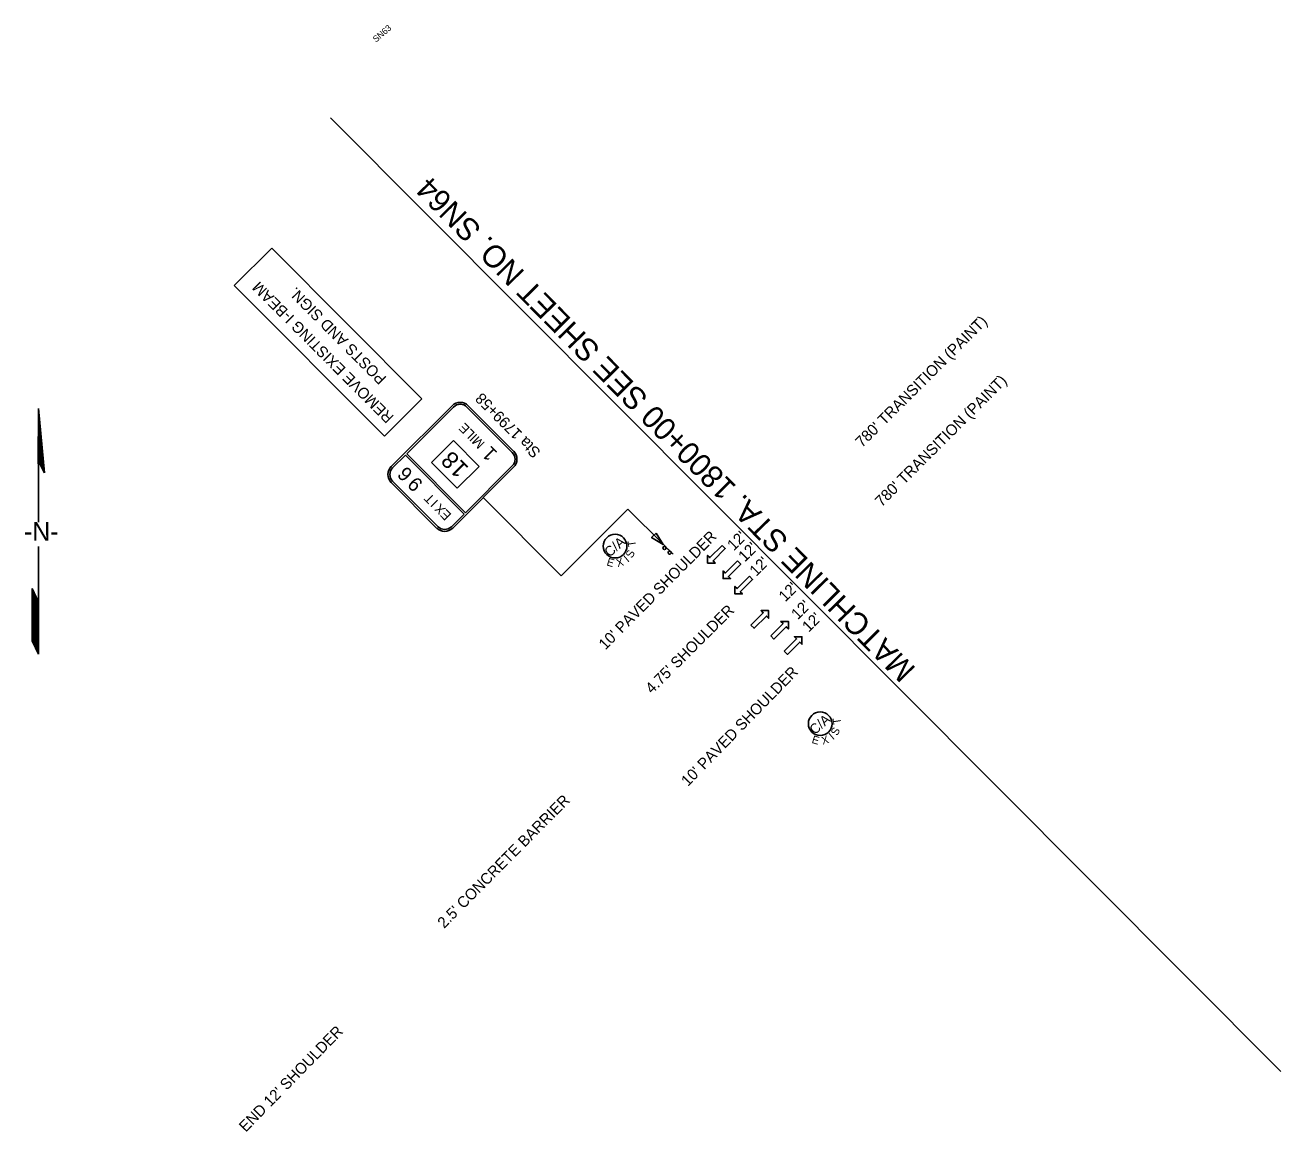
# Model space of a CAD drawing. Extents: x 1824788 to 1826426, y 1192883 to 1194457.
# Drawn here: x 1825629 to 1826426, y 1193755 to 1194457 of the extents above; entities that cross this region are included whole.
import ezdxf

# ---------------------------------------------------------------- set-up
doc = ezdxf.new("R2010")
doc.units = 0
for name, color, linetype in [('RD_HC_TX_Sta50', 7, 'Continuous'), ('RD_PD_Final_LnLine', 7, 'Continuous'), ('RD_PD_Final_TX', 7, 'Continuous'), ('RD_SHT_MatchLine', 7, 'Continuous'), ('RD_SHT_TX', 7, 'Continuous'), ('RD_Sketch1', 7, 'Continuous'), ('RD_Sketch8', 7, 'Continuous'), ('SN_P_Signs', 7, 'Continuous')]:
    doc.layers.add(name, color=color, linetype=linetype)

# ---------------------------------------------------------------- blocks, each defined once
blk = doc.blocks.new('SARRW2')
at = {"layer": 'RD_PD_Final_LnLine'}
blk.add_lwpolyline([(-12, 1.2), (-12, -1.2), (-2.83, -1.2), (-2.83, -2.83), (0, 0), (-2.83, 2.83), (-2.83, 1.2)], close=True, dxfattribs=at)

msp = doc.modelspace()

# ---------------------------------------------------------------- linework, layer by layer
at = {"layer": 'RD_SHT_MatchLine'}
msp.add_line((1825823.21, 1194398.41), (1826426.49, 1193793.21), dxfattribs=at)
at = {"layer": 'RD_Sketch1'}
for p, q in [((1825637.73, 1194213.93), (1825637.53, 1194178.77)), ((1825641.46, 1194173.23), (1825637.73, 1194213.93)), ((1825638.04, 1194180.17), (1825641.46, 1194173.23)), ((1825637.73, 1194179.06), (1825637.73, 1194157.24)), ((1825637.73, 1194157.24), (1825637.73, 1194141.77)), ((1825637.73, 1194126.32), (1825637.73, 1194100.55)), ((1825637.73, 1194100.55), (1825637.73, 1194058.03)), ((1825633.74, 1194085.49), (1825633.74, 1194099.66)), ((1825633.74, 1194099.66), (1825637.73, 1194091.1)), ((1825633.74, 1194066.59), (1825633.74, 1194085.49)), ((1825637.73, 1194058.03), (1825633.74, 1194066.59))]:
    msp.add_line(p, q, dxfattribs=at)
for points in [[(1825637.75, 1194179.37), (1825637.75, 1194213.81)], [(1825637.84, 1194179.63), (1825637.84, 1194212.78)], [(1825637.93, 1194179.89), (1825637.94, 1194211.75)], [(1825638.03, 1194180.15), (1825638.03, 1194210.71)], [(1825638.12, 1194180), (1825638.12, 1194209.68)], [(1825638.22, 1194179.81), (1825638.22, 1194208.65)], [(1825638.31, 1194179.61), (1825638.31, 1194207.62)], [(1825638.41, 1194179.42), (1825638.41, 1194206.58)], [(1825638.5, 1194179.23), (1825638.5, 1194205.55)], [(1825638.6, 1194179.04), (1825638.6, 1194204.52)], [(1825637.65, 1194179.11), (1825637.65, 1194199.89)], [(1825638.69, 1194178.85), (1825638.69, 1194203.49)], [(1825638.79, 1194178.66), (1825638.79, 1194202.45)], [(1825638.88, 1194178.46), (1825638.88, 1194201.42)], [(1825638.97, 1194178.27), (1825638.97, 1194200.39)], [(1825639.07, 1194178.08), (1825639.07, 1194199.36)], [(1825639.16, 1194177.89), (1825639.16, 1194198.32)], [(1825639.26, 1194177.7), (1825639.26, 1194197.29)], [(1825639.35, 1194177.51), (1825639.35, 1194196.26)], [(1825639.45, 1194177.31), (1825639.45, 1194195.23)], [(1825639.54, 1194177.12), (1825639.54, 1194194.19)], [(1825639.64, 1194176.93), (1825639.64, 1194193.16)], [(1825639.73, 1194176.74), (1825639.73, 1194192.13)], [(1825639.82, 1194176.55), (1825639.82, 1194191.1)], [(1825639.92, 1194176.35), (1825639.92, 1194190.06)], [(1825640.01, 1194176.16), (1825640.01, 1194189.03)], [(1825640.11, 1194175.97), (1825640.11, 1194188)], [(1825637.56, 1194178.85), (1825637.56, 1194183.99)], [(1825640.2, 1194175.78), (1825640.2, 1194186.97)], [(1825640.3, 1194175.59), (1825640.3, 1194185.93)], [(1825640.39, 1194175.4), (1825640.39, 1194184.9)], [(1825640.49, 1194175.2), (1825640.49, 1194183.87)], [(1825640.58, 1194175.01), (1825640.58, 1194182.84)], [(1825640.68, 1194174.82), (1825640.68, 1194181.8)], [(1825640.77, 1194174.63), (1825640.77, 1194180.77)], [(1825640.86, 1194174.44), (1825640.86, 1194179.74)], [(1825640.96, 1194174.25), (1825640.96, 1194178.71)], [(1825641.05, 1194174.05), (1825641.05, 1194177.67)], [(1825641.15, 1194173.86), (1825641.15, 1194176.64)], [(1825641.24, 1194173.67), (1825641.24, 1194175.61)], [(1825641.34, 1194173.48), (1825641.34, 1194174.58)], [(1825641.43, 1194173.29), (1825641.43, 1194173.54)], [(1825633.82, 1194066.43), (1825633.82, 1194099.5)], [(1825633.91, 1194066.22), (1825633.91, 1194099.29)], [(1825634.01, 1194066.02), (1825634.01, 1194099.09)], [(1825634.1, 1194065.82), (1825634.1, 1194098.89)], [(1825634.2, 1194065.61), (1825634.2, 1194098.69)], [(1825634.29, 1194065.41), (1825634.29, 1194098.48)], [(1825634.39, 1194065.21), (1825634.39, 1194098.28)], [(1825634.48, 1194065.01), (1825634.48, 1194098.08)], [(1825634.57, 1194064.8), (1825634.57, 1194097.88)], [(1825634.67, 1194064.6), (1825634.67, 1194097.67)], [(1825634.76, 1194064.4), (1825634.76, 1194097.47)], [(1825634.86, 1194064.2), (1825634.86, 1194097.27)], [(1825634.95, 1194063.99), (1825634.95, 1194097.06)], [(1825635.05, 1194063.79), (1825635.05, 1194096.86)], [(1825635.14, 1194063.59), (1825635.14, 1194096.66)], [(1825635.24, 1194063.39), (1825635.24, 1194096.46)], [(1825635.33, 1194063.18), (1825635.33, 1194096.25)], [(1825635.42, 1194062.98), (1825635.42, 1194096.05)], [(1825635.52, 1194062.78), (1825635.52, 1194095.85)], [(1825635.61, 1194062.58), (1825635.61, 1194095.65)], [(1825635.71, 1194062.37), (1825635.71, 1194095.44)], [(1825635.8, 1194062.17), (1825635.8, 1194095.24)], [(1825635.9, 1194061.97), (1825635.9, 1194095.04)], [(1825635.99, 1194061.76), (1825635.99, 1194094.84)], [(1825636.09, 1194061.56), (1825636.09, 1194094.63)], [(1825636.18, 1194061.36), (1825636.18, 1194094.43)], [(1825636.28, 1194061.16), (1825636.28, 1194094.23)], [(1825636.37, 1194060.95), (1825636.37, 1194094.02)], [(1825636.46, 1194060.75), (1825636.46, 1194093.82)], [(1825636.56, 1194060.55), (1825636.56, 1194093.62)], [(1825636.65, 1194060.35), (1825636.65, 1194093.42)], [(1825636.75, 1194060.14), (1825636.75, 1194093.21)], [(1825636.84, 1194059.94), (1825636.84, 1194093.01)], [(1825636.94, 1194059.74), (1825636.94, 1194092.81)], [(1825637.03, 1194059.54), (1825637.03, 1194092.61)], [(1825637.13, 1194059.33), (1825637.13, 1194092.4)], [(1825637.22, 1194059.13), (1825637.22, 1194092.2)], [(1825637.31, 1194058.93), (1825637.31, 1194092)], [(1825637.41, 1194058.73), (1825637.41, 1194091.8)], [(1825637.5, 1194058.52), (1825637.5, 1194091.59)], [(1825637.6, 1194058.32), (1825637.6, 1194091.39)], [(1825637.69, 1194058.12), (1825637.69, 1194091.19)]]:
    msp.add_lwpolyline(points, dxfattribs=at)
at = {"layer": 'RD_Sketch8'}
for centre in [(1826003.81, 1194126.61), (1826134.02, 1194013.92)]:
    msp.add_circle(centre, 7.5, dxfattribs=at)
at = {"layer": 'SN_P_Signs'}
for p, q in [((1825762.02, 1194292.03), (1825785.83, 1194315.76)), ((1825785.83, 1194315.76), (1825881.17, 1194220.16)), ((1825857.36, 1194196.42), (1825762.02, 1194292.03)), ((1825881.17, 1194220.16), (1825857.36, 1194196.42)), ((1825900.41, 1194215.74), (1825861.72, 1194177.16)), ((1825901.14, 1194193.55), (1825887.19, 1194179.65)), ((1825917.43, 1194177.22), (1825901.14, 1194193.55)), ((1825900.7, 1194138.08), (1825939.39, 1194176.66)), ((1825903.48, 1194163.32), (1825917.43, 1194177.22)), ((1825908.78, 1194147.82), (1825938.54, 1194177.51)), ((1825861.71, 1194166.98), (1825890.52, 1194138.09)), ((1825920.05, 1194157.37), (1825969.48, 1194107.79)), ((1825969.48, 1194107.79), (1826011.96, 1194150.15)), ((1826034.29, 1194127.76), (1826011.96, 1194150.15)), ((1825907.93, 1194146.98), (1825899.85, 1194138.93)), ((1826037.47, 1194124.57), (1826034.29, 1194127.76)), ((1826040.75, 1194121.58), (1826037.58, 1194124.77))]:
    msp.add_line(p, q, dxfattribs=at)
for points in [[(1825901.26, 1194214.9), (1825871.49, 1194185.21)], [(1825938.55, 1194185.99), (1825909.74, 1194214.88)], [(1825939.4, 1194186.84), (1825910.59, 1194215.73)], [(1825862.57, 1194176.31), (1825870.64, 1194184.36)], [(1825870.64, 1194184.36), (1825907.93, 1194146.98)], [(1825871.49, 1194185.21), (1825908.78, 1194147.82)], [(1825887.19, 1194179.65), (1825903.48, 1194163.32)], [(1825891.37, 1194138.94), (1825862.56, 1194167.83)]]:
    msp.add_lwpolyline(points, dxfattribs=at)
msp.add_lwpolyline([(1826029.84, 1194134.93), (1826034.26, 1194127.73), (1826026.97, 1194132.01)], close=True, dxfattribs=at)
for centre in [(1826035.16, 1194125.46), (1826038.44, 1194122.47)]:
    msp.add_circle(centre, 1, dxfattribs=at)
for centre, radius, start, end in [((1825905.5, 1194210.65), 7.2, 44.92051, 134.92051), ((1825905.5, 1194210.65), 6, 44.92051, 134.92051), ((1825934.31, 1194181.76), 6, 314.92051, 44.92051), ((1825934.31, 1194181.76), 7.2, 314.92051, 44.92051), ((1825866.81, 1194172.06), 7.2, 134.92051, 224.92051), ((1825866.81, 1194172.06), 6, 134.92051, 224.92051), ((1825895.62, 1194143.17), 7.2, 224.92051, 314.92051), ((1825895.62, 1194143.17), 6, 224.92051, 314.92051)]:
    msp.add_arc(centre, radius, start, end, dxfattribs=at)

# ---------------------------------------------------------------- block references
at = {"layer": 'RD_PD_Final_LnLine', "xscale": 1.2000000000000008}
for p, yscale, rotation in [((1826062.56, 1194115.89), -1.2000000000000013, -135.0673694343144), ((1826072.32, 1194106.06), -1.2000000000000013, -135.0673694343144), ((1826079.88, 1194096.26), -1.2000000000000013, -135.0673694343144), ((1826101.26, 1194085.66), 1.200000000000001, 44.88558225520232), ((1826113.82, 1194078.84), 1.200000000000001, 44.88558225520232), ((1826122.4, 1194069.11), 1.200000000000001, 44.88558225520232)]:
    msp.add_blockref('SARRW2', p, dxfattribs=dict(at, yscale=yscale, rotation=rotation))

# ---------------------------------------------------------------- texts
at = {"layer": 'RD_HC_TX_Sta50'}
for p in [(1826160.58, 1194188.78), (1826173.01, 1194151.17)]:
    msp.add_text("780' TRANSITION (PAINT)", height=7, rotation=44.90911, dxfattribs=at).set_placement(p)
at = {"layer": 'RD_PD_Final_TX'}
for s, rotation, p in [("10' PAVED SHOULDER", 45.20364, (1825997.57, 1194060.37)), ("12'", 44.726, (1826079.11, 1194123.32)), ("12'", 44.726, (1826086.16, 1194116.22)), ("12'", 44.726, (1826093.29, 1194107.04)), ("12'", 44.726, (1826111.82, 1194090.88)), ("12'", 44.726, (1826119.74, 1194079.55)), ("4.75' SHOULDER", 44.90911, (1826027.19, 1194032.52)), ("12'", 44.726, (1826126.72, 1194071.62)), ("10' PAVED SHOULDER", 45.7933, (1826050.02, 1193973.69)), ("2.5' CONCRETE BARRIER", 45.21099, (1825895.25, 1193883.66)), ("END 12' SHOULDER", 45.64245, (1825769.31, 1193754.32))]:
    msp.add_text(s, height=7, rotation=rotation, dxfattribs=at).set_placement(p)
at = {"layer": 'RD_SHT_TX'}
for s, height, rotation, p in [('SN63', 4, 40.38346, (1825852.02, 1194446.12)), ('MATCHLINE STA. 1800+00 SEE SHEET NO. SN64', 14.1726, 134.62781, (1826195.29, 1194048.97))]:
    msp.add_text(s, height=height, rotation=rotation, dxfattribs=at).set_placement(p)
at = {"layer": 'RD_Sketch1'}
msp.add_text('-N-', height=11.811, rotation=0, dxfattribs=at).set_placement((1825628.54, 1194130.03))
at = {"layer": 'RD_Sketch8'}
for s, height, rotation, p in [('C/A', 6.25, 40.38346, (1826000.29, 1194119.31)), ('S', 5, 62.1759, (1826014.56, 1194118.59)), ('T', 5, 98.56861, (1826017.22, 1194126.58)), ('E', 5, 343.59471, (1825998.08, 1194114.49)), ('X', 5, 16.02408, (1826005.38, 1194113.28)), ('I', 5, 40.18408, (1826011.89, 1194116.09)), ('C/A', 6.25, 40.38346, (1826130.5, 1194006.62)), ('T', 5, 98.56861, (1826147.43, 1194013.89)), ('E', 5, 343.59471, (1826128.29, 1194001.79)), ('X', 5, 16.02408, (1826135.6, 1194000.58)), ('I', 5, 40.18408, (1826142.11, 1194003.4)), ('S', 5, 62.1759, (1826144.77, 1194005.9))]:
    msp.add_text(s, height=height, rotation=rotation, dxfattribs=at).set_placement(p)
at = {"layer": 'SN_P_Signs'}
for s, height, rotation, p in [('REMOVE EXISTING I-BEAM', 6.9998, 134.92059, (1825863.79, 1194208.89)), ('POSTS AND SIGN.', 6.9998, 134.92059, (1825859.08, 1194233.44)), ('Sta 1799+58', 7, 134.92059, (1825957.01, 1194186.7)), ('MILE', 6, 134.92051, (1825921.43, 1194192.05)), ('1', 9, 134.92051, (1825929.62, 1194185.96)), ('18', 10.8, 134.92051, (1825911.38, 1194176.43)), ('6', 9, 134.92051, (1825875.96, 1194173.08)), ('9', 9, 134.92051, (1825882.39, 1194166.64)), ('T', 6, 134.92051, (1825889.71, 1194157.17)), ('I', 6, 134.92051, (1825891.82, 1194155.06)), ('X', 6, 134.92051, (1825896.63, 1194150.23)), ('E', 6, 134.92051, (1825900.26, 1194146.59))]:
    msp.add_text(s, height=height, rotation=rotation, dxfattribs=at).set_placement(p)

doc.saveas('drawing.dxf')
